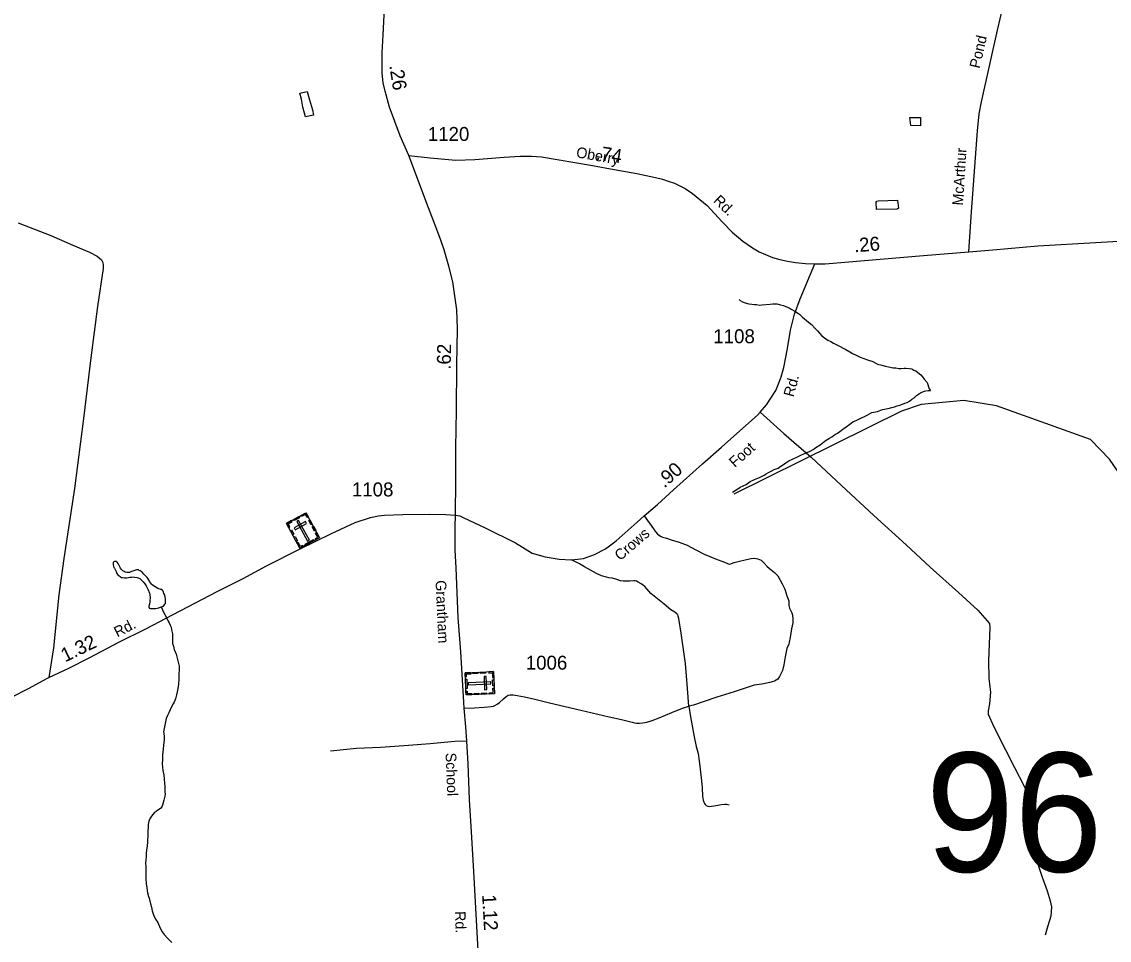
# Model space of a CAD drawing. Extents: x 2206922 to 2357709, y 510027 to 673830.
# Drawn here: x 2241724 to 2251460, y 541278 to 549500 of the extents above; entities that cross this region are included whole.
import ezdxf

# ---------------------------------------------------------------- set-up
doc = ezdxf.new("R2010")
doc.units = 0
for name, color, linetype in [('Exist Cultural Cemetery CELL', 7, 'Continuous'), ('Exist Hydrographic Misc Water Feature', 7, 'Continuous'), ('Exist Road Non-System Type 51', 7, 'Continuous'), ('Exist Road Secondary Mileage Hundredths English Label', 7, 'Continuous'), ('Exist Road Secondary Structure Standard Bridge Number Label', 7, 'Continuous'), ('Exist Road Secondary Type 51 Attributed', 7, 'Continuous'), ('Exist Road Secondary Type 51 Label', 7, 'Continuous'), ('Exist Road Secondary Type 51 Number Label', 7, 'Continuous')]:
    doc.layers.add(name, color=color, linetype=linetype)

msp = doc.modelspace()

# ---------------------------------------------------------------- linework, layer by layer
at = {"layer": 'Exist Cultural Cemetery CELL'}
for points in [[(2244092.9, 545009.9), (2244267.8, 545105.1), (2244389.5, 544881.4), (2244214.6, 544786.3)], [(2244113.6, 544971.9), (2244123.6, 544977.3), (2244108.2, 545005.6), (2244143.8, 545025), (2244138.5, 545034.7), (2244092.9, 545009.9)], [(2244158, 545045.3), (2244203.5, 545070.1), (2244209, 545060.1), (2244163.5, 545035.3)], [(2244202.7, 545036.3), (2244186.3, 545027.4), (2244283.2, 544849.2), (2244299.6, 544858.1)], [(2244288.6, 545067), (2244278.6, 545061.6), (2244263.3, 545089.9), (2244227.6, 545070.5), (2244222.3, 545080.3), (2244267.9, 545105)], [(2244313.5, 544997.3), (2244292.8, 545035.4), (2244302.8, 545040.8), (2244323.5, 545002.8)], [(2244149, 544906.7), (2244128.3, 544944.8), (2244138.3, 544950.2), (2244159, 544912.2)], [(2244161.3, 544969.7), (2244170.2, 544953.2), (2244273.7, 545009.5), (2244264.7, 545025.9)], [(2244345, 544939.4), (2244324.3, 544977.5), (2244334.3, 544982.9), (2244355, 544944.9)], [(2244181.1, 544847.7), (2244160.4, 544885.7), (2244170.4, 544891.2), (2244191.1, 544853.1)], [(2244259.6, 544823.8), (2244334.1, 544864.3), (2244339.6, 544854.3), (2244265, 544813.8)], [(2244360.4, 544865.5), (2244354.9, 544875.6), (2244374.2, 544886.1), (2244354.9, 544921.6), (2244364.7, 544927), (2244389.5, 544881.4)], [(2244243.6, 544802.1), (2244238.1, 544812.2), (2244218.8, 544801.7), (2244199.5, 544837.2), (2244189.7, 544831.9), (2244214.5, 544786.3)], [(2245948, 543682.4), (2245955.5, 543483.5), (2245701.1, 543473.8), (2245693.5, 543672.7)], [(2245694.8, 543639.7), (2245706.3, 543640.1), (2245705.5, 543662.1), (2245745.9, 543663.6), (2245745.4, 543674.8), (2245693.6, 543672.8)], [(2245763.4, 543675.4), (2245806.7, 543677.1), (2245807.1, 543665.7), (2245763.8, 543664.1)], [(2245830.6, 543678), (2245873.9, 543679.6), (2245874.3, 543668.2), (2245831, 543666.6)], [(2245904.7, 543680.8), (2245905.1, 543669.4), (2245937.3, 543670.7), (2245938.8, 543630.1), (2245949.9, 543630.5), (2245948, 543682.4)], [(2245707.2, 543615.8), (2245710.4, 543531), (2245699, 543530.5), (2245695.8, 543615.3)], [(2245922.8, 543572.4), (2245922.1, 543591), (2245719.5, 543583.3), (2245720.2, 543564.7)], [(2245881.5, 543639), (2245862.9, 543638.3), (2245867.3, 543520.7), (2245886, 543521.4)], [(2245950.8, 543608.4), (2245952.7, 543556.6), (2245941.3, 543556.2), (2245939.4, 543608)], [(2245699.8, 543506.9), (2245711.3, 543507.3), (2245712.1, 543485.4), (2245752.5, 543486.9), (2245753, 543475.8), (2245701.1, 543473.8)], [(2245772.9, 543487.9), (2245816.2, 543489.5), (2245816.6, 543478.2), (2245773.3, 543476.5)], [(2245838.8, 543490.4), (2245882, 543492), (2245882.5, 543480.6), (2245839.2, 543479)], [(2245912.2, 543481.7), (2245911.8, 543493.1), (2245943.9, 543494.3), (2245942.4, 543534.8), (2245953.5, 543535.3), (2245955.5, 543483.4)]]:
    msp.add_lwpolyline(points, close=True, dxfattribs=at)
at = {"layer": 'Exist Hydrographic Misc Water Feature'}
for points in [[(2244277.4, 548875.7), (2244300.2, 548800.1), (2244325.2, 548710.3), (2244335.4, 548662.5), (2244263.3, 548649.9), (2244238.9, 548735.5), (2244228.4, 548805.6), (2244214.1, 548859.3), (2244277.4, 548875.7)], [(2249675, 548642.1), (2249768.7, 548642.9), (2249769.5, 548569), (2249683.4, 548572.3), (2249675, 548642.1)], [(2249373.2, 547885.9), (2249379.3, 547894.3), (2249391.4, 547898.1), (2249563.3, 547901.4), (2249573.7, 547831.8), (2249561.8, 547821.3), (2249377.5, 547820), (2249373.2, 547885.9)], [(2248147, 547012.8), (2248155, 547005.5), (2248175.3, 546994), (2248199.4, 546983.8), (2248233.1, 546974.3), (2248259.1, 546972.4), (2248283.1, 546968.7), (2248301.2, 546968.9), (2248327.2, 546962.9), (2248349.3, 546965.3), (2248423.2, 546972), (2248447.2, 546976.1), (2248462.9, 546976.1), (2248485.1, 546974.4), (2248515.4, 546966.6), (2248542.9, 546958.8), (2248571, 546948.9), (2248593.8, 546939.4), (2248613.4, 546927.5), (2248645.2, 546909.7), (2248677.8, 546887.7), (2248689.7, 546877.9), (2248713.7, 546856.4), (2248748, 546824.4), (2248768.3, 546810.9), (2248794.3, 546789.1), (2248826.5, 546755), (2248848.8, 546733.4), (2248866.9, 546711.6), (2248887.2, 546687.5), (2248909.7, 546669.9), (2248941.7, 546650.1), (2248967.8, 546636.4), (2248992, 546622.6), (2249021.9, 546606.7), (2249052.1, 546592.9), (2249077.9, 546579.2), (2249100, 546565.4), (2249136.1, 546543.7), (2249160.5, 546529.9), (2249194.6, 546514.2), (2249229, 546496.5), (2249294.8, 546473.2), (2249343.2, 546457.3), (2249385.1, 546436), (2249423.4, 546426.2), (2249457, 546416.6), (2249483.3, 546410.7), (2249525.3, 546403.1), (2249549.3, 546401.1), (2249574.9, 546397.3), (2249595.4, 546397.4), (2249623.5, 546397.6), (2249639.3, 546398.1), (2249667, 546396.3), (2249691, 546392.3), (2249711.1, 546382.4), (2249727.7, 546374.7), (2249747.4, 546360.7), (2249771.8, 546339.2), (2249787.6, 546321.4), (2249804, 546299.5), (2249828.4, 546269.5), (2249836.4, 546253.6), (2249842.3, 546231.6), (2249848.7, 546213.6), (2249858.9, 546197.9)], [(2248086.9, 545289.9), (2248134.7, 545318.4), (2248154.7, 545332.4), (2248208.7, 545356.7), (2248243.9, 545383), (2248283.9, 545403.4), (2248328, 545419.8), (2248371.5, 545442.1), (2248389.3, 545454.4), (2248409.6, 545466.3), (2248433, 545476.6), (2248461.3, 545491), (2248496.8, 545505.1), (2248520.8, 545521.3), (2248542.7, 545537.5), (2248564.4, 545551.6), (2248590.7, 545568), (2248630.1, 545588.4), (2248670.2, 545606.7), (2248705.9, 545622.8), (2248747.8, 545641.2), (2248782, 545655.1), (2248807.6, 545671.5), (2248833.3, 545687.9), (2248871.2, 545713.8), (2248900.9, 545736.1), (2248926.8, 545754.5), (2248956.7, 545772.7), (2248976.6, 545784.7), (2249000.6, 545801), (2249026.2, 545817.4), (2249046.3, 545833.4), (2249076, 545853.7), (2249103.5, 545873.9), (2249137.6, 545896.3), (2249165.4, 545918.5), (2249200.9, 545932.6), (2249243, 545953), (2249267.2, 545965.2), (2249293, 545977.5), (2249334.4, 546001.7), (2249384.6, 546011.9), (2249430.4, 546028.6), (2249480, 546038.9), (2249512, 546047.1), (2249538, 546053.2), (2249562, 546061.4), (2249584, 546067.8), (2249607.7, 546078), (2249629.9, 546086), (2249649.6, 546092.4), (2249671.5, 546104.5), (2249691.2, 546120.6), (2249713.1, 546134.7), (2249735.3, 546152.9), (2249752.9, 546166.8), (2249770.8, 546177.1), (2249781.2, 546183.3), (2249805, 546193.5), (2249819, 546197.5), (2249838.8, 546199.7), (2249858.9, 546197.9)], [(2252560.5, 542421.7), (2252351.5, 542570.2), (2252014.4, 542983.7), (2251854.5, 543324.7), (2251734.5, 543691.2), (2251680.6, 544223.6), (2251656.4, 545139.1), (2251578.5, 545412.9), (2251460.6, 545585.8), (2251292.5, 545759.7), (2250449.5, 546062.1), (2250157.5, 546110.6), (2249774.5, 546072.4), (2249600.6, 546013.6), (2248098.6, 545269.9)], [(2242971.6, 544262.8), (2242979.8, 544263.2), (2242986, 544267.1), (2242991.7, 544269.1), (2242999.5, 544277.3), (2243005.5, 544285.3), (2243009.4, 544293.2), (2243011.2, 544301.5), (2243011.6, 544311.2), (2243011.2, 544319.3), (2243011.6, 544329.4), (2243011.4, 544335.1), (2243007.1, 544353.2), (2243001.2, 544373.1), (2242996.9, 544383.1), (2242992.8, 544397.1), (2242988.7, 544403), (2242984.6, 544406.9), (2242982.7, 544410.8), (2242976.6, 544417), (2242968.8, 544419), (2242962.6, 544420.7), (2242950.7, 544422.9), (2242940.7, 544426.9), (2242918.3, 544440.3), (2242902.1, 544450.5), (2242892.3, 544458.1), (2242883.9, 544466.2), (2242877.9, 544474), (2242868.1, 544488.1), (2242864.2, 544498), (2242855.8, 544511.9), (2242845.9, 544523.9), (2242833.4, 544535.9), (2242825.9, 544545.6), (2242815.6, 544555.6), (2242801.7, 544571.5), (2242793.5, 544579.2), (2242783.4, 544585.2), (2242775.2, 544589.3), (2242767.4, 544593.3), (2242761.5, 544593), (2242749.6, 544593.2), (2242733.6, 544588.7), (2242717.2, 544582.6), (2242705.5, 544578.7), (2242699.3, 544574.8), (2242687.4, 544570.5), (2242675.8, 544568.6), (2242663.2, 544570.5), (2242649.5, 544574.2), (2242639.5, 544578.1), (2242627.2, 544586), (2242617.3, 544596), (2242606.9, 544609.8), (2242598.9, 544627.7), (2242592.9, 544639.9), (2242586.8, 544649.7), (2242579, 544661.4), (2242570.6, 544667.6), (2242564.6, 544667.6), (2242555, 544667.5), (2242549, 544665.2), (2242544.9, 544663.3), (2242542.9, 544659.2), (2242541, 544655.4), (2242540.8, 544651.4), (2242543.1, 544639.3), (2242545.1, 544627.2), (2242549.2, 544615.3), (2242552.9, 544607.4), (2242559.5, 544595.5), (2242567.5, 544579.6), (2242575.5, 544561.4), (2242581.4, 544551.6), (2242591.9, 544541.9), (2242608.1, 544529.8), (2242613.8, 544526), (2242625.9, 544524.2), (2242643.8, 544522.3), (2242663.9, 544522.5), (2242679.9, 544524.6), (2242692.2, 544526.8), (2242707.7, 544528.9), (2242720, 544530.7), (2242734.2, 544529), (2242758.2, 544524.9), (2242779.9, 544515.2), (2242798.2, 544499.5), (2242810.1, 544487.5), (2242824.2, 544467.5), (2242838.4, 544449.6), (2242846.8, 544433.7), (2242854.8, 544415.9), (2242864.8, 544392.1), (2242868.9, 544378.1), (2242871, 544368), (2242873.2, 544348.2), (2242873.2, 544338.1), (2242871.4, 544326.2)], [(2242971.6, 544262.8), (2242983.9, 544235), (2242992.2, 544215.1), (2243004.7, 544195.4), (2243010.2, 544183.2), (2243022.7, 544161.4), (2243035, 544135.6), (2243043, 544119.4), (2243053.3, 544099.7), (2243061.5, 544079.8), (2243065.4, 544057.7), (2243069.7, 544033.9), (2243071.9, 544019.8), (2243071.9, 543991.8), (2243074.2, 543961.9), (2243074.2, 543933.9), (2243080.7, 543910.2), (2243086.9, 543882.1), (2243104.9, 543838.4), (2243111.7, 543814.3), (2243119.5, 543780.3), (2243132, 543732.6), (2243132.4, 543694.4), (2243128.7, 543666.6), (2243131, 543634.6), (2243129.1, 543612.6), (2243127.5, 543570.6), (2243121.7, 543530.5), (2243116, 543500.6), (2243110.3, 543474.3), (2243100.4, 543438.5), (2243088.5, 543410.3), (2243079.1, 543394.2), (2243064.9, 543366), (2243053.5, 543340.1), (2243039.3, 543313.8), (2243027.6, 543290.1), (2243018, 543262), (2243010.2, 543233.9), (2243004.5, 543203.9), (2242998.5, 543173.6), (2242993.2, 543143.7), (2242996.7, 543131.8), (2242997.5, 543098), (2242997.5, 543067.9), (2242991.9, 543023.8), (2242988.5, 542987.8), (2242984.8, 542937.7), (2242982.9, 542895.8), (2242980.9, 542855.9), (2242983.1, 542826), (2242987.8, 542797.7), (2242994.2, 542759.8), (2242998.7, 542719.9), (2243002.4, 542684), (2243004.9, 542650), (2243005.3, 542630), (2243005.3, 542606.1), (2243007.3, 542585.9), (2243003.6, 542568.3), (2242995.8, 542532.1), (2242986.2, 542499.9), (2242980.5, 542478.1), (2242974.5, 542468), (2242966.5, 542457.9), (2242940.9, 542441.4), (2242926.7, 542431.4), (2242908.7, 542417.5), (2242884.9, 542389.1), (2242873.4, 542371), (2242861.5, 542345.2), (2242855.6, 542314.8), (2242853.9, 542285), (2242852.3, 542257), (2242852.9, 542207), (2242850.7, 542178.9), (2242848.8, 542154.8), (2242847, 542123.1), (2242841.4, 542085), (2242838, 542058.8), (2242836.1, 542029), (2242834.5, 541996.8), (2242832.4, 541966.8), (2242833, 541937.1), (2242835.1, 541890.9), (2242835.3, 541869), (2242835.5, 541827.2), (2242837.7, 541787.1), (2242842.7, 541747), (2242850.7, 541703.3), (2242858.9, 541671.2), (2242863.2, 541655.5), (2242875.5, 541605.4), (2242885.5, 541573.5), (2242891.7, 541541.7), (2242904, 541505.8), (2242922.4, 541465.8), (2242940.9, 541436.2), (2242963.2, 541386.2), (2242979.6, 541354.5)], [(2242871.4, 544326.2), (2242869.1, 544316), (2242869.7, 544304.1), (2242867.9, 544290.2), (2242867.7, 544286.2), (2242864.2, 544276.2), (2242861.9, 544268), (2242861.7, 544264), (2242861.9, 544259.9), (2242863.8, 544256), (2242865.6, 544252.1), (2242870.1, 544250.2), (2242875.7, 544248.1), (2242892.1, 544246.5), (2242903.8, 544246.3), (2242921.6, 544248.5), (2242936, 544250.8), (2242949.9, 544252.7), (2242971.6, 544262.8)], [(2242979.6, 541354.5), (2242999.9, 541328.4), (2243028.2, 541296.9), (2243068.2, 541259.3)]]:
    msp.add_lwpolyline(points, dxfattribs=at)
at = {"layer": 'Exist Road Non-System Type 51'}
for points in [[(2241690.2, 547701), (2241983, 547585.3), (2242181.6, 547501.1), (2242330.1, 547438.3), (2242398.3, 547400.8), (2242438.6, 547367.2), (2242448.7, 547343.4), (2242452.9, 547321.3), (2242451.3, 547291.3), (2242402.4, 546950.4), (2242340.7, 546491.3), (2242277.3, 545948.7), (2242195, 545322.1), (2242101.6, 544696), (2242054.8, 544368.8), (2242006.4, 543896.3), (2241964.7, 543630.9)], [(2248334.2, 546006), (2248547, 545814.5), (2248791.6, 545603.4), (2249062.8, 545349.7), (2249353.6, 545080.1), (2249642.5, 544817.6), (2249857, 544619), (2250108.7, 544390.2), (2250284.4, 544232.5), (2250386.7, 544114.6), (2250392, 544077.3), (2250380.1, 543779.5), (2250381.4, 543625), (2250392, 543547.9), (2250397.3, 543497.3), (2250386.7, 543393.5), (2250376.1, 543332.4), (2250376.1, 543300.4), (2250426.6, 543188.7), (2250530.3, 542981.2), (2250612.7, 542824.2), (2250697.8, 542656.6), (2250772.3, 542499.6), (2250804.2, 542427.8), (2250809.5, 542401.1), (2250814.8, 542350.6), (2250814.8, 542289.4), (2250812.2, 542236.2), (2250801.5, 542201.6), (2250798.9, 542167), (2250804.2, 542092.5), (2250812.2, 541994.1), (2250828.1, 541932.9), (2250860, 541842.4), (2250905.2, 541720), (2250931.8, 541632.2), (2250942.5, 541576.4), (2250939.8, 541531.1), (2250937.1, 541493.9), (2250910.5, 541406.1), (2250886.6, 541323.6)], [(2247297, 545076.1), (2247325.1, 545034.7), (2247359.5, 544990.1), (2247384.9, 544953.2), (2247404, 544926.5), (2247416.7, 544912.5), (2247429.5, 544903.5), (2247442.2, 544894.6), (2247461.3, 544885.7), (2247496.9, 544878.1), (2247538.9, 544862.8), (2247608.9, 544842.4), (2247680.1, 544813.2), (2247757.7, 544773.7), (2247832.8, 544735.5), (2247933.3, 544690.9), (2248014.7, 544662.9), (2248041.5, 544651.5), (2248059.3, 544643.8), (2248061.8, 544645.1), (2248077.1, 544651.5), (2248102.5, 544660.4), (2248136.9, 544668), (2248210.7, 544685.8), (2248255.2, 544694.8), (2248284.5, 544697.3), (2248312.5, 544692.2), (2248343, 544679.5), (2248371, 544652.7), (2248396.4, 544624.7), (2248433.3, 544594.2), (2248462.6, 544571.3), (2248493.1, 544539.4), (2248532.6, 544469.4), (2248556.8, 544421.1), (2248574.6, 544362.5), (2248589.8, 544316.7), (2248592.4, 544275.9), (2248597.5, 544250.5), (2248608.9, 544226.3), (2248616.6, 544209.7), (2248624.2, 544188.1), (2248628, 544156.3), (2248626.7, 544119.3), (2248615.3, 544064.6), (2248602.6, 543989.5), (2248593.7, 543947.5), (2248589.8, 543928.4), (2248573.7, 543889.9), (2248559.7, 543816.1), (2248547, 543743.5), (2248535.5, 543693.9), (2248517.7, 543657), (2248507.5, 543637.9), (2248493.5, 543613.7), (2248464.3, 543598.4), (2248419.7, 543584.4), (2248348.5, 543570.4), (2248280.7, 543561.7), (2248102.5, 543500.6), (2247947.3, 543453.5), (2247834.1, 543416.6), (2247738.6, 543383.5), (2247696.7, 543374.6)], [(2247696.7, 543374.6), (2247682.7, 543532.5), (2247664.8, 543755.2), (2247627.9, 544027.7), (2247607.6, 544157.5), (2247601.2, 544180.4), (2247596.1, 544191.9), (2247587.2, 544200.8), (2247569.4, 544214.8), (2247533.8, 544235.2), (2247474, 544287.4), (2247356.9, 544381.6), (2247300.9, 544444), (2247269.1, 544469.4), (2247242.4, 544483.4), (2247228.4, 544491.1), (2247215.7, 544496.2), (2247204.3, 544496.2), (2247167.4, 544493.6), (2247133, 544491.1), (2247108.8, 544491.1), (2247084.6, 544496.2), (2247041.4, 544510.2), (2247008.3, 544520.3), (2246980.3, 544522.9), (2246957.4, 544528), (2246912.9, 544540.7), (2246869.6, 544559.8), (2246816.2, 544591.6), (2246761.5, 544620.9), (2246715.7, 544648.9), (2246646.5, 544684.6)], [(2245685.7, 543355.5), (2245776.7, 543359.3), (2245864.5, 543365.7), (2245925.5, 543370.8), (2245945.9, 543373.3), (2245959.9, 543379.7), (2245979, 543389.9), (2246000.6, 543405.1), (2246036.2, 543438.2), (2246060.4, 543461.2), (2246076.9, 543471.3), (2246096, 543475.2), (2246124, 543473.9), (2246159.6, 543467.5), (2246223.3, 543456.1), (2246317.4, 543435.7), (2246447.2, 543402.6), (2246729.7, 543337.7), (2246984.1, 543277.8), (2247093.6, 543254.9), (2247189, 543229.5), (2247208.1, 543223.1), (2247227.2, 543221.8), (2247253.9, 543221.8), (2247283.1, 543223.1), (2247320, 543230.7), (2247367.1, 543246), (2247429.5, 543267.7), (2247542.7, 543316), (2247639.4, 543354.2), (2247696.7, 543374.6)], [(2247696.7, 543374.6), (2247709.4, 543277.8), (2247725.9, 543197.6), (2247743.7, 543098.3), (2247762.8, 543013), (2247779.4, 542949.4), (2247787, 542884.5), (2247798.4, 542808.1), (2247809.9, 542703.7), (2247816.3, 542642.6), (2247818.8, 542568.7), (2247825.2, 542531.8), (2247829, 542514), (2247835.3, 542502.5), (2247843, 542492.4), (2247850.6, 542484.7), (2247864.6, 542477.1), (2247881.1, 542475.8), (2247938.4, 542483.5), (2247988, 542493.6), (2248016, 542497.5), (2248033.8, 542494.9), (2248058, 542489.8)], [(2245708, 543060.1), (2245601.1, 543056.3), (2245379.7, 543035.3), (2245186.9, 543022), (2244936.9, 543004.8), (2244719.3, 542993.3), (2244486.5, 542970.4)]]:
    msp.add_lwpolyline(points, dxfattribs=at)
at = {"layer": 'Exist Road Secondary Type 51 Attributed'}
for points in [[(2250203.2, 547439.3), (2250225.3, 547798), (2250257.1, 548199.7), (2250280.7, 548523.1), (2250295.9, 548676.2), (2250315.3, 548783.5), (2250457.9, 549423.4), (2250606, 550047.4), (2250658.6, 550289.8), (2250722.3, 550519.8), (2250768, 550684.6), (2250834.4, 550904.8), (2250906.4, 551079.3), (2251000.5, 551262.2), (2251313.4, 551857.1), (2251498.9, 552208.2)], [(2245189.1, 548301.5), (2245112.9, 548477.4), (2245016, 548736.4), (2244975.9, 548877.7), (2244959.3, 548953.9), (2244951, 549039.1), (2244951, 549136), (2244951, 549221.9), (2244957.9, 549382.6), (2244970.6, 549619.8)], [(2245607.8, 545083.2), (2245609.1, 545396.6), (2245610.3, 545687.1), (2245615.4, 546019.6), (2245619.2, 546426.8), (2245624.3, 546750.4), (2245617.9, 546921.7), (2245610.3, 546982.6), (2245597.2, 547066.9), (2245582.4, 547172.9), (2245547.6, 547312.5), (2245506.4, 547458.1), (2245477.7, 547535.8), (2245441, 547639.6), (2245364.9, 547834), (2245189.1, 548301.5)], [(2245189.1, 548301.5), (2245380.1, 548282.8), (2245611.3, 548260.6), (2245780.2, 548266.2), (2246043.4, 548288), (2246185.8, 548295.3), (2246288.2, 548298), (2246378.2, 548289.7), (2246833.7, 548212.9), (2247027.8, 548176.1), (2247229.6, 548140.8), (2247397.1, 548106.2), (2247459.4, 548091), (2247512, 548073), (2247567.4, 548055), (2247608.9, 548032.8), (2247664.3, 548006.5), (2247728, 547963.5), (2247859.5, 547854.1), (2247995.1, 547710.1), (2248083.7, 547615.2), (2248179.3, 547534.9), (2248265.1, 547476), (2248324.6, 547440), (2248382.7, 547415), (2248446.4, 547390.1), (2248511.5, 547370.7), (2248579.3, 547355.5), (2248649.9, 547345.8), (2248739.9, 547336.1), (2248823, 547331.9)], [(2250203.2, 547439.3), (2250416.3, 547457.3), (2250821.7, 547492.8), (2251336.7, 547524), (2252012.6, 547562.9), (2252508.1, 547589), (2252817.9, 547611.6), (2253083.3, 547645.6), (2253203.1, 547668.6), (2253375, 547702.5)], [(2248823, 547331.9), (2248915.7, 547332.6), (2249797.5, 547408.8), (2250203.2, 547439.3)], [(2245607.8, 545083.2), (2245645.8, 545076.8), (2245682.6, 545060.3), (2245872.8, 544969), (2246142.9, 544834.5), (2246294.2, 544743.7), (2246410.5, 544708.8), (2246536.4, 544689.9), (2246646.5, 544684.6), (2246752.3, 544695.5), (2246851.9, 544730.3), (2246949.6, 544783.1), (2247045, 544853.8), (2247233.5, 545021.3), (2247297, 545076.1), (2247416, 545178.8), (2247559, 545309.9), (2247819, 545541.8), (2247989.6, 545693.1), (2248152.2, 545838.4), (2248311, 545979.7), (2248334.2, 546006), (2248390, 546071.8), (2248435.9, 546137.9), (2248474.3, 546199.4), (2248504.4, 546272.7), (2248522.1, 546322.3), (2248545.5, 546405.3), (2248580.1, 546575.5), (2248604.8, 546737.6), (2248641.1, 546883.1), (2248692.8, 547019.6), (2248823, 547331.9)], [(2241626.9, 543452.5), (2241791.2, 543534.9), (2241909.5, 543598.8), (2241964.7, 543630.9), (2242144.6, 543714.6), (2242331.8, 543809.5), (2242592.1, 543946.4), (2242835.7, 544065.6), (2243080.5, 544192.5), (2243473.6, 544400.6), (2243704.4, 544514.8), (2243916.1, 544629), (2244216.7, 544782.5), (2244495.7, 544919.1), (2244707.4, 545017.2), (2244846.9, 545062.9), (2244917.9, 545078.1), (2244972.5, 545084.5), (2245134.8, 545088.3), (2245373.2, 545090.8), (2245520.3, 545089.5), (2245607.8, 545083.2)], [(2245867.7, 540496.2), (2245860.1, 540558.6), (2245843.1, 540744.1), (2245816.2, 541077.7), (2245789.1, 541566.1), (2245769.6, 541893), (2245750.8, 542248.6), (2245732.4, 542538.3), (2245719.8, 542858.1), (2245708, 543060.1), (2245699.1, 543187.8), (2245685.7, 543355.5), (2245681.3, 543409.6), (2245656, 543858.8), (2245631.9, 544167.1), (2245614.1, 544611.2), (2245605.3, 544768.5), (2245602.7, 544979.1), (2245607.8, 545083.2)]]:
    msp.add_lwpolyline(points, dxfattribs=at)

# ---------------------------------------------------------------- texts
at = {"layer": 'Exist Road Secondary Mileage Hundredths English Label'}
for s, rotation, p in [('.26', 279.09628, (2245013.4, 549107.6)), ('.74', 351.48209, (2246858.5, 548266.8)), ('.26', 4.48498, (2249179.4, 547435.5)), ('.62', 89.04824, (2245564.2, 546383.8)), ('.90', 41.73046, (2247477.1, 545320.6)), ('1.32', 25.94951, (2242111.9, 543764.5)), ('1.12', 273.17322, (2245845.1, 541685.5))]:
    msp.add_text(s, height=125, rotation=rotation, dxfattribs=at).set_placement(p)
at = {"layer": 'Exist Road Secondary Structure Standard Bridge Number Label'}
msp.add_text('96', height=1066.27, dxfattribs=at).set_placement((2249816.1, 541890.8))
at = {"layer": 'Exist Road Secondary Type 51 Label'}
for s, rotation, p in [('Pond', 76.91016, (2250299.3, 549076.3)), ('Oberry', 349.86671, (2246682.3, 548287.8)), ('McArthur', 86.34208, (2250149.7, 547852.8)), ('Rd.', 316.45886, (2247908.8, 547890.6)), ('Rd.', 74.85206, (2248632.9, 546135.6)), ('Foot', 41.56864, (2248107.5, 545504.9)), ('Crows', 40.79464, (2247081.3, 544670.7)), ('Grantham', 272.65891, (2245427.9, 544498.6)), ('Rd.', 27.03666, (2242579.4, 543987.6)), ('School', 272.25598, (2245518.1, 542954.8)), ('Rd.', 272.26005, (2245600.9, 541536.8))]:
    msp.add_text(s, height=95, rotation=rotation, dxfattribs=at).set_placement(p)
at = {"layer": 'Exist Road Secondary Type 51 Number Label'}
for s, p in [('1120', (2245358.7, 548432.7)), ('1108', (2247914.9, 546622.1)), ('1108', (2244679.2, 545250.8)), ('1006', (2246236, 543700.2))]:
    msp.add_text(s, height=125, dxfattribs=at).set_placement(p)

doc.saveas('drawing.dxf')
